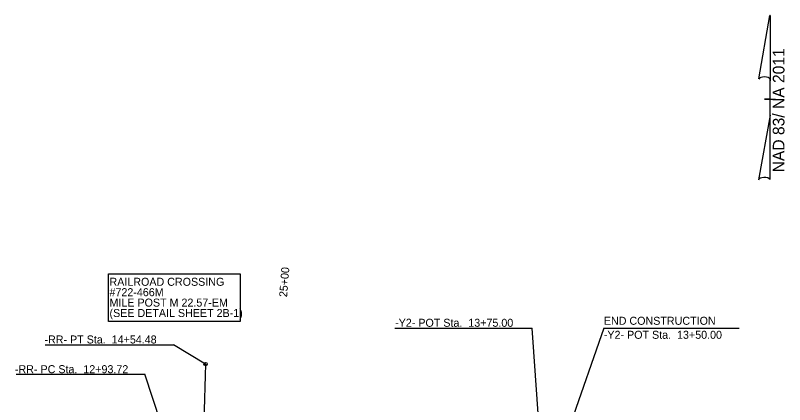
# Model space of a CAD drawing. Extents: x 1755545 to 1761252, y 736169 to 737766.
# Drawn here: x 1756972 to 1757645, y 737162 to 737502 of the extents above; entities that cross this region are included whole.
import ezdxf

# ---------------------------------------------------------------- set-up
doc = ezdxf.new("R2010")
doc.units = 0
for name, color, linetype in [('Exist Horizontal Alignment Station Label', 7, 'Continuous'), ('Prop Dimension', 7, 'Continuous'), ('Prop Horizontal Alignment Station Label', 7, 'Continuous'), ('Prop Horizontal Alignment Tick Label', 7, 'Continuous'), ('Prop North Arrow NAD83 for Plan Sheets CELL', 7, 'Continuous'), ('Raster_Level_0', 7, 'Continuous')]:
    doc.layers.add(name, color=color, linetype=linetype)

msp = doc.modelspace()

# ---------------------------------------------------------------- linework, layer by layer
at = {"layer": 'Exist Horizontal Alignment Station Label'}
for p, q in [((1756998.17, 737214.18), (1757110.54, 737214.18)), ((1757138.5, 737197.44), (1757110.54, 737214.18)), ((1756972.82, 737188.57), (1757085.26, 737188.57)), ((1757135.47, 737036.72), (1757085.26, 737188.57))]:
    msp.add_line(p, q, dxfattribs=at)
msp.add_circle((1757138.5, 737197.44), 1.5, dxfattribs=at)
at = {"layer": 'Prop Dimension'}
msp.add_lwpolyline([(1757053.65, 737276.24), (1757168.77, 737276.24), (1757168.77, 737234.76), (1757053.65, 737234.76)], close=True, dxfattribs=at)
at = {"layer": 'Prop Horizontal Alignment Station Label'}
for p, q in [((1757303.79, 737228.79), (1757424.01, 737228.79)), ((1757432.72, 737101.83), (1757424.01, 737228.79)), ((1757486.62, 737228.79), (1757433.41, 737076.84)), ((1757486.62, 737228.79), (1757604.84, 737228.79))]:
    msp.add_line(p, q, dxfattribs=at)
at = {"layer": 'Prop North Arrow NAD83 for Plan Sheets CELL'}
for p, q in [((1757621.99, 737446.74), (1757631.83, 737502.36)), ((1757631.89, 737502.36), (1757631.83, 737502.36)), ((1757631.89, 737502.36), (1757631.83, 737502.36)), ((1757631.89, 737502.36), (1757631.89, 737445)), ((1757631.89, 737415.24), (1757631.89, 737446.68)), ((1757631.89, 737445), (1757631.89, 737446.62)), ((1757627.09, 737429.16), (1757627.03, 737429.16)), ((1757631.35, 737429.16), (1757627.09, 737429.16)), ((1757627.15, 737429.16), (1757636.75, 737429.16)), ((1757631.89, 737415.24), (1757621.87, 737358.54)), ((1757631.95, 737358.78), (1757631.89, 737415.24))]:
    msp.add_line(p, q, dxfattribs=at)
for centre, start_param, end_param in [((1757626.95, 737446.15), 0.216388, 2.908219), ((1757626.95, 737358.34), 0.201328, 3.141593)]:
    msp.add_ellipse(centre, major_axis=(5.08, -0.04), ratio=0.461098, start_param=start_param, end_param=end_param, dxfattribs=at)
at = {"layer": 'Raster_Level_0'}
msp.add_arc((1762390.7, 737018.29), 5255.26, 178.04642, 179.79908, dxfattribs=at)

# ---------------------------------------------------------------- texts
at = {"layer": 'Exist Horizontal Alignment Station Label'}
for s, p in [('-RR- PT Sta.  14+54.48', (1756997.64, 737215.47)), ('-RR- PC Sta.  12+93.72', (1756971.81, 737189.49))]:
    msp.add_text(s, height=7, rotation=360, dxfattribs=at).set_placement(p)
at = {"layer": 'Prop Dimension'}
for s, p in [('RAILROAD CROSSING ', (1757054.49, 737265.92)), ('#722-466M', (1757054.49, 737256.82)), ('MILE POST M 22.57-EM', (1757054.49, 737247.72)), ('(SEE DETAIL SHEET 2B-1)', (1757054.49, 737238.62))]:
    msp.add_text(s, height=7, dxfattribs=at).set_placement(p)
at = {"layer": 'Prop Horizontal Alignment Station Label'}
for s, p in [('-Y2- POT Sta.  13+75.00', (1757304.17, 737230.08)), ('END CONSTRUCTION', (1757486.63, 737231.82)), ('-Y2- POT Sta.  13+50.00', (1757486.63, 737219.57))]:
    msp.add_text(s, height=7, rotation=360, dxfattribs=at).set_placement(p)
at = {"layer": 'Prop Horizontal Alignment Tick Label'}
msp.add_text('25+00', height=7, rotation=85.49152, dxfattribs=at).set_placement((1757209.72, 737255.77))
at = {"layer": 'Prop North Arrow NAD83 for Plan Sheets CELL'}
msp.add_text('NAD 83/ NA 2011', height=10.2, rotation=90, dxfattribs=at).set_placement((1757644.51, 737365.13))

doc.saveas('drawing.dxf')
